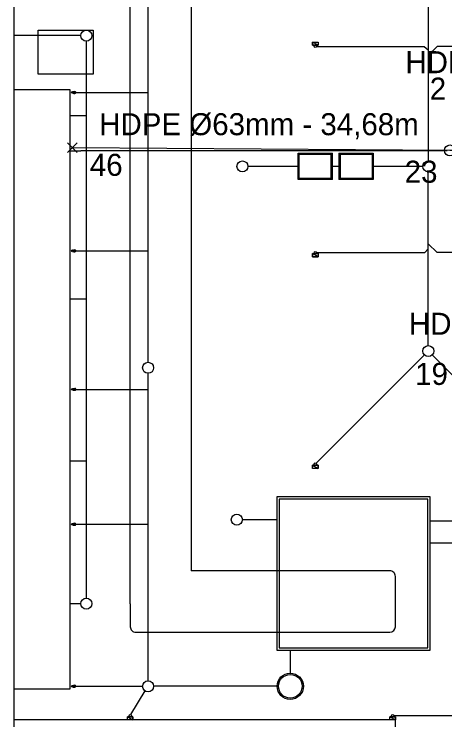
# Model space of a CAD drawing. Extents: x -263964 to -263544, y -1242317 to -1242020.
# Drawn here: x -263964.1 to -263925.1, y -1242255 to -1242190.9 of the extents above; entities that cross this region are included whole.
import ezdxf

# ---------------------------------------------------------------- set-up
doc = ezdxf.new("R2010")
doc.units = 0
for name, color, linetype in [('KFA_KOORDINACNA_SITUACIA_DSP_SEDA', 7, 'Continuous'), ('KFA_SO_50-1-II_BODY', 7, 'Continuous'), ('KFA_SO_50-1-II_SUPATKA', 7, 'Continuous'), ('KFA_SO_50-1-II_VODOVODNE_PRIPOJKY', 7, 'Continuous'), ('POPIS', 7, 'Continuous'), ('RAM_NA_TLAC_A3_1-100', 7, 'Continuous')]:
    doc.layers.add(name, color=color, linetype=linetype)

msp = doc.modelspace()

# ---------------------------------------------------------------- linework, layer by layer
at = {"layer": 'KFA_KOORDINACNA_SITUACIA_DSP_SEDA'}
for p, q in [((-263948.093, -1242087.901), (-263948.093, -1242241.458)), ((-263953.617, -1242244.458), (-263953.617, -1242093.307)), ((-263926.593, -1242155.252), (-263926.593, -1242204.252)), ((-263952, -1242222.527), (-263952, -1242182)), ((-263958.097, -1242192.883), (-263964.149, -1242192.883)), ((-263957.597, -1242243.932), (-263957.597, -1242193.383)), ((-263937.093, -1242193.752), (-263937.093, -1242193.462)), ((-263937.093, -1242193.462), (-263936.593, -1242193.462)), ((-263936.593, -1242193.752), (-263937.093, -1242193.462)), ((-263936.593, -1242193.752), (-263937.093, -1242193.462)), ((-263937.093, -1242193.462), (-263937.093, -1242193.752)), ((-263936.593, -1242193.752), (-263937.093, -1242193.752)), ((-263937.093, -1242193.752), (-263936.593, -1242193.752)), ((-263936.743, -1242193.852), (-263926.953, -1242193.852)), ((-263936.593, -1242193.462), (-263936.593, -1242193.752)), ((-263926.953, -1242193.852), (-263926.593, -1242194.178)), ((-263925.798, -1242193.852), (-263926.593, -1242194.648)), ((-263920.944, -1242193.852), (-263925.798, -1242193.852)), ((-263964.149, -1242197.782), (-263959.093, -1242197.782)), ((-263964.149, -1242197.782), (-263959.097, -1242197.782)), ((-263964.149, -1242252.182), (-263964.149, -1242197.782)), ((-263964.149, -1242197.782), (-263959.097, -1242197.782)), ((-263959.097, -1242197.782), (-263959.093, -1242252.182)), ((-263959.097, -1242197.782), (-263959.097, -1242252.182)), ((-263959.093, -1242197.782), (-263959.093, -1242252.182)), ((-263958.799, -1242197.962), (-263958.762, -1242197.962)), ((-263958.799, -1242198.102), (-263958.762, -1242198.102)), ((-263958.762, -1242197.962), (-263958.742, -1242197.942)), ((-263958.762, -1242198.102), (-263958.742, -1242198.122)), ((-263958.742, -1242197.942), (-263958.637, -1242197.942)), ((-263958.742, -1242198.122), (-263958.637, -1242198.122)), ((-263958.575, -1242198.032), (-263952, -1242198.032)), ((-263959.097, -1242200.132), (-263957.597, -1242200.132)), ((-263959.097, -1242203.332), (-263958.097, -1242203.332)), ((-263924.893, -1242203.332), (-263958.097, -1242203.332)), ((-263938.393, -1242203.552), (-263935.293, -1242203.552)), ((-263938.393, -1242205.952), (-263938.393, -1242203.552)), ((-263938.293, -1242205.852), (-263938.293, -1242203.652)), ((-263938.293, -1242203.652), (-263935.393, -1242203.652)), ((-263935.393, -1242205.852), (-263935.393, -1242203.652)), ((-263935.293, -1242205.952), (-263935.293, -1242203.552)), ((-263934.693, -1242203.552), (-263931.593, -1242203.552)), ((-263934.693, -1242203.552), (-263934.693, -1242205.952)), ((-263934.593, -1242203.652), (-263934.593, -1242205.852)), ((-263934.593, -1242203.652), (-263931.693, -1242203.652)), ((-263931.693, -1242203.652), (-263931.693, -1242205.852)), ((-263931.593, -1242203.552), (-263931.593, -1242205.952)), ((-263938.393, -1242204.752), (-263942.945, -1242204.752)), ((-263934.693, -1242204.752), (-263935.293, -1242204.752)), ((-263927.093, -1242204.752), (-263931.593, -1242204.752)), ((-263926.593, -1242221.011), (-263926.593, -1242205.252)), ((-263935.293, -1242205.952), (-263938.393, -1242205.952)), ((-263935.393, -1242205.852), (-263938.293, -1242205.852)), ((-263931.593, -1242205.952), (-263934.693, -1242205.952)), ((-263931.693, -1242205.852), (-263934.593, -1242205.852)), ((-263925.798, -1242212.562), (-263926.593, -1242211.767)), ((-263958.799, -1242212.337), (-263958.762, -1242212.337)), ((-263958.762, -1242212.337), (-263958.742, -1242212.317)), ((-263958.742, -1242212.317), (-263958.637, -1242212.317)), ((-263958.575, -1242212.407), (-263952, -1242212.407)), ((-263926.919, -1242212.562), (-263926.593, -1242212.237)), ((-263958.799, -1242212.477), (-263958.762, -1242212.477)), ((-263958.762, -1242212.477), (-263958.742, -1242212.497)), ((-263958.742, -1242212.497), (-263958.637, -1242212.497)), ((-263937.093, -1242212.952), (-263937.093, -1242212.662)), ((-263937.093, -1242212.662), (-263936.593, -1242212.662)), ((-263936.593, -1242212.952), (-263937.093, -1242212.662)), ((-263936.593, -1242212.952), (-263937.093, -1242212.662)), ((-263937.093, -1242212.662), (-263937.093, -1242212.952)), ((-263936.593, -1242212.952), (-263937.093, -1242212.952)), ((-263937.093, -1242212.952), (-263936.593, -1242212.952)), ((-263936.743, -1242212.562), (-263926.919, -1242212.562)), ((-263936.593, -1242212.662), (-263936.593, -1242212.952)), ((-263916.443, -1242212.562), (-263925.798, -1242212.562)), ((-263959.097, -1242216.782), (-263957.597, -1242216.782)), ((-263936.772, -1242231.691), (-263926.947, -1242221.865)), ((-263916.414, -1242231.691), (-263926.24, -1242221.865)), ((-263952, -1242251.432), (-263952, -1242223.527)), ((-263958.799, -1242224.912), (-263958.762, -1242224.912)), ((-263958.799, -1242225.052), (-263958.762, -1242225.052)), ((-263958.762, -1242224.912), (-263958.742, -1242224.892)), ((-263958.762, -1242225.052), (-263958.742, -1242225.072)), ((-263958.742, -1242224.892), (-263958.637, -1242224.892)), ((-263958.742, -1242225.072), (-263958.637, -1242225.072)), ((-263958.575, -1242224.982), (-263952, -1242224.982)), ((-263959.097, -1242231.482), (-263957.597, -1242231.482)), ((-263937.093, -1242231.862), (-263936.593, -1242231.862)), ((-263937.093, -1242232.152), (-263937.093, -1242231.862)), ((-263937.093, -1242231.862), (-263936.593, -1242232.152)), ((-263937.093, -1242231.862), (-263936.593, -1242232.152)), ((-263936.593, -1242231.862), (-263937.093, -1242231.862)), ((-263936.593, -1242232.152), (-263937.093, -1242232.152)), ((-263936.593, -1242231.862), (-263936.593, -1242232.152)), ((-263936.593, -1242232.152), (-263936.593, -1242231.862)), ((-263926.43, -1242234.749), (-263940.33, -1242234.749)), ((-263940.33, -1242234.749), (-263940.33, -1242248.649)), ((-263926.43, -1242248.649), (-263926.43, -1242234.749)), ((-263926.63, -1242234.949), (-263940.13, -1242234.949)), ((-263940.13, -1242234.949), (-263940.13, -1242248.449)), ((-263926.63, -1242248.449), (-263926.63, -1242234.949)), ((-263958.799, -1242237.162), (-263958.762, -1242237.162)), ((-263958.799, -1242237.302), (-263958.762, -1242237.302)), ((-263958.762, -1242237.162), (-263958.742, -1242237.142)), ((-263958.762, -1242237.302), (-263958.742, -1242237.322)), ((-263958.742, -1242237.142), (-263958.637, -1242237.142)), ((-263958.742, -1242237.322), (-263958.637, -1242237.322)), ((-263958.575, -1242237.232), (-263952, -1242237.232)), ((-263940.33, -1242236.811), (-263943.454, -1242236.811)), ((-263919.13, -1242236.949), (-263926.43, -1242236.949)), ((-263907.219, -1242238.949), (-263926.43, -1242238.949)), ((-263930.081, -1242241.458), (-263948.093, -1242241.458)), ((-263929.582, -1242246.53), (-263929.581, -1242241.959)), ((-263959.097, -1242244.432), (-263958.097, -1242244.432)), ((-263953.617, -1242244.458), (-263953.619, -1242246.529)), ((-263953.119, -1242247.03), (-263930.082, -1242247.03)), ((-263940.33, -1242248.649), (-263926.43, -1242248.649)), ((-263940.13, -1242248.449), (-263926.63, -1242248.449)), ((-263939.13, -1242248.649), (-263939.13, -1242250.737)), ((-263958.799, -1242251.862), (-263958.762, -1242251.862)), ((-263958.799, -1242252.002), (-263958.762, -1242252.002)), ((-263958.762, -1242251.862), (-263958.742, -1242251.842)), ((-263958.762, -1242252.002), (-263958.742, -1242252.022)), ((-263958.742, -1242251.842), (-263958.637, -1242251.842)), ((-263958.742, -1242252.022), (-263958.637, -1242252.022)), ((-263958.575, -1242251.932), (-263952.5, -1242251.932)), ((-263940.302, -1242251.932), (-263951.5, -1242251.932)), ((-263959.093, -1242252.182), (-263964.149, -1242252.182)), ((-263959.093, -1242252.182), (-263964.149, -1242252.182)), ((-263959.097, -1242252.182), (-263964.149, -1242252.182)), ((-263953.57, -1242254.506), (-263952.26, -1242252.359)), ((-263953.87, -1242254.692), (-263953.37, -1242254.692)), ((-263953.87, -1242254.982), (-263953.87, -1242254.692)), ((-263953.87, -1242254.692), (-263953.37, -1242254.982)), ((-263953.87, -1242254.692), (-263953.37, -1242254.982)), ((-263953.37, -1242254.692), (-263953.87, -1242254.692)), ((-263953.37, -1242254.692), (-263953.37, -1242254.982)), ((-263953.37, -1242254.982), (-263953.37, -1242254.692)), ((-263930.08, -1242254.692), (-263929.58, -1242254.692)), ((-263930.08, -1242254.982), (-263930.08, -1242254.692)), ((-263930.08, -1242254.692), (-263929.58, -1242254.982)), ((-263930.08, -1242254.692), (-263929.58, -1242254.982)), ((-263929.58, -1242254.692), (-263930.08, -1242254.692)), ((-263929.73, -1242254.592), (-263920.595, -1242254.592)), ((-263929.58, -1242254.692), (-263929.58, -1242254.982)), ((-263929.58, -1242254.982), (-263929.58, -1242254.692)), ((-263953.37, -1242254.982), (-263953.87, -1242254.982)), ((-263929.58, -1242254.982), (-263930.08, -1242254.982))]:
    msp.add_line(p, q, dxfattribs=at)
msp.add_lwpolyline([(-263961.968, -1242192.382), (-263956.968, -1242192.382), (-263956.968, -1242196.382), (-263961.968, -1242196.382)], close=True, dxfattribs=at)
for points in [[(-263929.58, -1242254.982), (-263964.149, -1242254.982)], [(-263964.149, -1242263.982), (-263929.58, -1242263.982), (-263929.58, -1242254.982)]]:
    msp.add_lwpolyline(points, dxfattribs=at)
for centre, radius in [((-263957.597, -1242192.883), 0.5), ((-263936.843, -1242193.852), 0.1), ((-263958.847, -1242198.032), 0.085), ((-263958.847, -1242198.032), 0.0625), ((-263958.637, -1242198.032), 0.0625), ((-263943.445, -1242204.752), 0.5), ((-263926.593, -1242204.752), 0.5), ((-263958.847, -1242212.407), 0.085), ((-263958.847, -1242212.407), 0.0625), ((-263958.637, -1242212.407), 0.0625), ((-263936.843, -1242212.562), 0.1), ((-263926.593, -1242221.511), 0.5), ((-263952, -1242223.027), 0.5), ((-263958.847, -1242224.982), 0.085), ((-263958.847, -1242224.982), 0.0625), ((-263958.637, -1242224.982), 0.0625), ((-263936.843, -1242231.762), 0.1), ((-263943.954, -1242236.811), 0.5), ((-263958.847, -1242237.232), 0.085), ((-263958.847, -1242237.232), 0.0625), ((-263958.637, -1242237.232), 0.0625), ((-263957.597, -1242244.432), 0.5), ((-263939.107, -1242251.932), 1.195), ((-263939.107, -1242251.932), 1.075), ((-263952, -1242251.932), 0.5), ((-263958.847, -1242251.932), 0.085), ((-263958.847, -1242251.932), 0.0625), ((-263958.637, -1242251.932), 0.0625), ((-263953.62, -1242254.592), 0.1), ((-263929.83, -1242254.592), 0.1)]:
    msp.add_circle(centre, radius, dxfattribs=at)
for centre, radius, start, end in [((-263958.637, -1242198.032), 0.09, 270, 90), ((-263958.637, -1242212.407), 0.09, 270, 90), ((-263958.637, -1242224.982), 0.09, 270, 90), ((-263958.637, -1242237.232), 0.09, 270, 90), ((-263930.081, -1242241.958), 0.5, 359.97854, 89.99994), ((-263953.119, -1242246.53), 0.5, 179.95255, 270), ((-263930.082, -1242246.53), 0.5, 270, 359.97854), ((-263958.637, -1242251.932), 0.09, 270, 90)]:
    msp.add_arc(centre, radius, start, end, dxfattribs=at)
at = {"layer": 'KFA_SO_50-1-II_BODY'}
for p, q in [((-263959.31, -1242203.493), (-263958.426, -1242202.609)), ((-263958.426, -1242203.493), (-263959.31, -1242202.609))]:
    msp.add_line(p, q, dxfattribs=at)
at = {"layer": 'KFA_SO_50-1-II_SUPATKA'}
msp.add_circle((-263924.631, -1242203.301), 0.5, dxfattribs=at)
at = {"layer": 'KFA_SO_50-1-II_VODOVODNE_PRIPOJKY'}
msp.add_lwpolyline([(-263924.185, -1242203.3), (-263924.631, -1242203.301), (-263958.868, -1242203.051)], dxfattribs=at)
at = {"layer": 'RAM_NA_TLAC_A3_1-100'}
msp.add_lwpolyline([(-263964.149, -1242020.359), (-263544.149, -1242020.359), (-263544.149, -1242317.359), (-263964.149, -1242317.359)], close=True, dxfattribs=at)

# ---------------------------------------------------------------- texts
at = {"layer": 'KFA_SO_50-1-II_BODY'}
for s, p in [('2', (-263926.46, -1242198.691)), ('46', (-263957.286, -1242205.607)), ('23', (-263928.734, -1242206.23)), ('19', (-263927.785, -1242224.581))]:
    msp.add_text(s, height=2, dxfattribs=at).set_placement(p)
at = {"layer": 'POPIS'}
for s, p in [('HDPE Ø110mm - 9,93m', (-263928.671, -1242196.289)), ('HDPE Ø63mm - 34,68m', (-263956.439, -1242201.918)), ('HDPE Ø63mm - 21,00m', (-263928.352, -1242220.03))]:
    msp.add_text(s, height=2, dxfattribs=at).set_placement(p)

doc.saveas('drawing.dxf')
